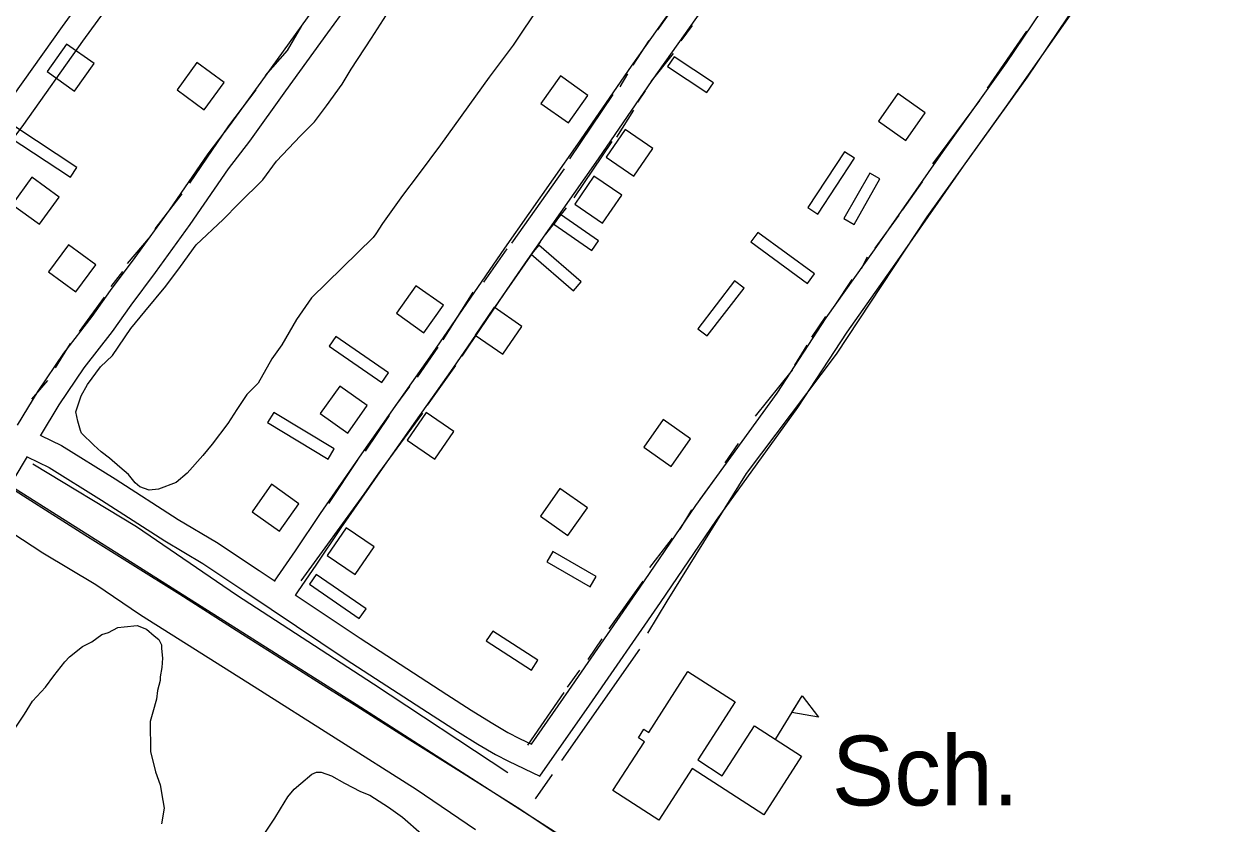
# Model space of a CAD drawing. Extents: x 3535183 to 3573198, y 534952 to 560562.
# Drawn here: x 3547982 to 3549418, y 545165 to 546115 of the extents above; entities that cross this region are included whole.
import ezdxf

# ---------------------------------------------------------------- set-up
doc = ezdxf.new("R2010")
doc.units = 0
for name, color, linetype in [('V-BLDG-IDEN', 7, 'Continuous'), ('V-BLDG-OTLN', 7, 'Continuous'), ('V-RAIL-TRAK', 7, 'Continuous'), ('V-ROAD-CNTR', 7, 'Continuous'), ('V-SITE-VEGE', 7, 'Continuous'), ('V-TOPO-SHOR', 7, 'Continuous')]:
    doc.layers.add(name, color=color, linetype=linetype)

msp = doc.modelspace()

# ---------------------------------------------------------------- linework, layer by layer
at = {"layer": 'V-BLDG-OTLN'}
msp.add_line((3548875.1, 545265.8), (3548906.1, 545317.2), dxfattribs=at)
for points in [[(3548032.1, 546091.2), (3548009, 546058.6), (3548041.7, 546035.5), (3548064.8, 546068.1)], [(3548793.1, 546033.7), (3548800.8, 546045.4), (3548754.1, 546076.2), (3548746.4, 546064.5)], [(3548195.7, 546013.3), (3548219.4, 546045.5), (3548187.1, 546069.2), (3548163.5, 546037)], [(3548628.5, 545997.6), (3548651.6, 546030.2), (3548619, 546053.4), (3548595.9, 546020.8)], [(3549029.5, 545976.6), (3549052.5, 546009.4), (3549019.8, 546032.4), (3548996.8, 545999.6)], [(3548036.8, 545933), (3548044.5, 545944.6), (3547971.7, 545992.7), (3547964, 545981)], [(3548696, 545989.9), (3548673.4, 545956.9), (3548706.4, 545934.3), (3548729, 545967.3)], [(3548913.2, 545897), (3548924.9, 545889.3), (3548968.4, 545955.7), (3548956.7, 545963.4)], [(3547999.8, 545877.2), (3548023.3, 545909.6), (3547990.9, 545933), (3547967.4, 545900.6)], [(3548658.9, 545934.2), (3548636.3, 545901.3), (3548669.2, 545878.6), (3548691.9, 545911.6)], [(3548955.9, 545883.9), (3548968.1, 545877), (3548998.7, 545931), (3548986.5, 545937.9)], [(3548656.4, 545846), (3548664.4, 545857.6), (3548619.2, 545888.8), (3548611.2, 545877.3)], [(3548853.6, 545867.5), (3548845.3, 545856.2), (3548912.6, 545807), (3548920.9, 545818.3)], [(3548043, 545796.9), (3548066.7, 545829.1), (3548034.5, 545852.8), (3548010.8, 545820.6)], [(3548634.6, 545798.2), (3548643.7, 545808.8), (3548593.4, 545852.3), (3548584.2, 545841.7)], [(3548456.7, 545748.4), (3548479.9, 545781), (3548447.3, 545804.2), (3548424.1, 545771.5)], [(3548782.4, 545753.1), (3548793.5, 545744.6), (3548837.2, 545801.5), (3548826, 545810)], [(3548540.2, 545778.6), (3548517.5, 545745.6), (3548550.5, 545723), (3548573.1, 545755.9)], [(3548352.1, 545743.9), (3548344.2, 545732.4), (3548406.8, 545689.2), (3548414.8, 545700.7)], [(3548366.2, 545629.2), (3548389.3, 545661.8), (3548356.7, 545685), (3548333.5, 545652.4)], [(3548278.3, 545653.8), (3548271, 545641.8), (3548342.9, 545598.3), (3548350.2, 545610.3)], [(3548459.3, 545653.8), (3548436.7, 545620.8), (3548469.6, 545598.2), (3548492.3, 545631.1)], [(3548750.7, 545589.6), (3548773.7, 545622.4), (3548741, 545645.3), (3548718, 545612.6)], [(3548285.1, 545512.7), (3548308.3, 545545.3), (3548275.7, 545568.4), (3548252.5, 545535.8)], [(3548628, 545507.6), (3548651, 545540.3), (3548618.2, 545563.3), (3548595.3, 545530.5)], [(3548364.5, 545516.6), (3548341.9, 545483.6), (3548374.9, 545461), (3548397.5, 545494)], [(3548610, 545488.5), (3548603, 545476.4), (3548654.5, 545446.6), (3548661.5, 545458.7)], [(3548380, 545409), (3548388, 545420.6), (3548328.8, 545461.2), (3548320.9, 545449.7)], [(3548538.5, 545394), (3548530.9, 545382.2), (3548584.6, 545347.7), (3548592.2, 545359.4)], [(3548826.5, 545309.8), (3548782.1, 545240.9), (3548811.3, 545222.1), (3548849.6, 545281.4), (3548905.6, 545245.3), (3548860.7, 545175.6), (3548775.4, 545230.6), (3548736, 545169.4), (3548681.4, 545204.6), (3548718.8, 545262.6), (3548711.8, 545267.1), (3548718.3, 545277.3), (3548724, 545273.6), (3548770.5, 545345.8)], [(3548906.1, 545317.2), (3548925.8, 545291.8), (3548894.2, 545297.4)]]:
    msp.add_lwpolyline(points, close=True, dxfattribs=at)
at = {"layer": 'V-RAIL-TRAK'}
msp.add_lwpolyline([(3547950.8, 545573.8), (3547985.3, 545552), (3548054, 545508.5), (3548110.8, 545472.7), (3548166.7, 545437.9), (3548233.7, 545395.1), (3548301.5, 545352.3), (3548341.6, 545326.8), (3548377.1, 545304.9), (3548436.8, 545266.8), (3548504.7, 545224.5), (3548567.4, 545185), (3548617.3, 545152)], dxfattribs=at)
at = {"layer": 'V-ROAD-CNTR'}
for points in [[(3549783, 548504.4), (3549676.2, 548359.9), (3549570.7, 548220.8), (3549457.8, 548069.1), (3549430.3, 548030.7), (3549356.4, 547927.2), (3549237.3, 547764.4), (3549120.1, 547605.6), (3548994.7, 547436.4), (3548915.5, 547331.8), (3548821.3, 547200.7), (3548722.7, 547067.2), (3548658.1, 546975.3), (3548586.3, 546878.4), (3548504.1, 546765.1), (3548454.3, 546692.9), (3548372.6, 546586), (3548290.4, 546473.6), (3548233.2, 546393.6), (3548168.8, 546306.2), (3548097.8, 546210.1), (3548026.7, 546112.1), (3547956.6, 546013.5)], [(3549446.2, 548001.3), (3549380.7, 547909.6), (3549261.5, 547746.6), (3549144.2, 547587.8), (3549018.7, 547418.4), (3548939.6, 547314), (3548845.6, 547183), (3548747.1, 547049.6), (3548682.4, 546957.7), (3548610.5, 546860.7), (3548528.6, 546747.8), (3548478.5, 546675.2), (3548396.6, 546568.1), (3548314.7, 546456), (3548257.5, 546376), (3548192.9, 546288.4), (3548122, 546192.3), (3548051.1, 546094.6), (3547980.9, 545995.8), (3547872.1, 545850.4), (3547819.9, 545780.2), (3547795.3, 545743.1)], [(3550407.3, 544022.4), (3550107.6, 544208.9), (3549713.8, 544462.2), (3549285.5, 544731.9), (3548967.9, 544929.2), (3548660.1, 545124.6), (3548376.2, 545306.9), (3547938.6, 545583), (3547735, 545714.5), (3547336.2, 545960.9), (3547019.4, 546160.3), (3546450.8, 546522.1), (3546030.5, 546792), (3545657.2, 547024.6), (3545377, 547202.9), (3545241.8, 547291.6), (3544939.7, 547479.7), (3544491.7, 547765.6), (3544295.4, 547891.8)], [(3549592.5, 547279.4), (3549546.2, 547215.7), (3549478.9, 547121.4), (3549417, 547032), (3549341.3, 546923.9), (3549252.5, 546794.5), (3549173.8, 546681), (3549119.4, 546607), (3549062.2, 546526.3), (3548977.2, 546404.6), (3548922.7, 546327.1), (3548852.5, 546226.7), (3548796.1, 546144.9), (3548727.8, 546047.9), (3548663.9, 545955.1), (3548577.1, 545831.6), (3548491.1, 545706.4), (3548407, 545587.2), (3548358.1, 545516.7), (3548328.5, 545472.4), (3548307.3, 545441.9), (3548304.3, 545437.2)], [(3549392.4, 547049.2), (3549316.6, 546941), (3549227.8, 546811.5), (3549149.3, 546698.5), (3549095, 546624.6), (3549037.7, 546543.6), (3548952.6, 546421.8), (3548898.1, 546344.3), (3548827.9, 546243.8), (3548771.5, 546162.1), (3548703.1, 546065), (3548639.3, 545972.2), (3548552.5, 545848.8), (3548466.5, 545723.6), (3548382.5, 545604.4), (3548333.4, 545533.6), (3548303.7, 545489.3), (3548282.4, 545458.5), (3548279, 545453.3)], [(3548303.8, 545437.1), (3548380.9, 545385.4), (3548483.9, 545318.7), (3548512.8, 545300.2), (3548536.5, 545285.4), (3548556.5, 545273.6), (3548570.5, 545266.4), (3548584.6, 545259.6), (3548629, 545323.2), (3548713.1, 545444.9), (3548779.8, 545543), (3548876.6, 545676.5), (3548935, 545765.9), (3548992.3, 545847), (3549073.7, 545963.6), (3549149.3, 546069), (3549221.5, 546176.5), (3549315.6, 546305.8), (3549341.6, 546343.7), (3549402.5, 546432.6), (3549529.1, 546614), (3549614.2, 546734.9), (3549701.7, 546857.3), (3549787, 546986)], [(3547973.7, 545638.6), (3547998.2, 545678.8), (3548028.8, 545724.2), (3548062.5, 545767.7), (3548084.5, 545798.6), (3548113.6, 545837.8), (3548154.4, 545894.1), (3548200.3, 545960.7), (3548225.7, 545994), (3548268.5, 546053.3), (3548318.3, 546122.3), (3548386.1, 546215.4), (3548442.7, 546292.8), (3548485.1, 546351.8), (3548530.9, 546415.7), (3548567.8, 546465.9), (3548609.7, 546523.7), (3548667.8, 546605), (3548709.7, 546662.3), (3548751.3, 546721.4), (3548778.1, 546758.5)], [(3548001.1, 545625.9), (3548023.5, 545662.6), (3548053.1, 545706.7), (3548086.5, 545749.8), (3548108.8, 545781), (3548137.8, 545820), (3548178.9, 545876.8), (3548224.6, 545943.1), (3548249.8, 545976.1), (3548292.8, 546035.8), (3548342.6, 546104.7), (3548410.3, 546197.7), (3548467, 546275.2), (3548509.5, 546334.4), (3548555.2, 546398.1), (3548592, 546448.2), (3548634, 546506.1), (3548692.1, 546587.4), (3548734.1, 546644.8), (3548775.7, 546704), (3548802.4, 546740.9)], [(3547985.1, 545601), (3548011.3, 545588.2), (3548073.8, 545549.5), (3548149, 545501.2), (3548194.2, 545474.2), (3548244.1, 545441), (3548275.2, 545420.2), (3548364.4, 545360.4), (3548467.7, 545293.5), (3548496.8, 545274.8), (3548521, 545259.8), (3548542, 545247.3), (3548557.1, 545239.5), (3548594.6, 545221.6), (3548653.6, 545306.1), (3548737.8, 545428), (3548804.4, 545525.8), (3548901.3, 545659.4), (3548959.8, 545749.1), (3549016.9, 545829.7), (3549098.2, 545946.3), (3549173.9, 546051.9), (3549246.1, 546159.3)], [(3548001.6, 545626.4), (3548025.9, 545614.5), (3548089.8, 545574.9), (3548164.8, 545526.7), (3548210.1, 545499.6), (3548260.8, 545466), (3548280, 545453.1)], [(3547970.9, 545576.8), (3547984.5, 545599.2), (3547985.7, 545601.2)]]:
    msp.add_lwpolyline(points, dxfattribs=at)
at = {"layer": 'V-SITE-VEGE'}
for points in [[(3548218.1, 545883), (3548236.8, 545902), (3548265.3, 545929.9), (3548281.7, 545952.2), (3548310.2, 545982.4), (3548326.7, 545999.1), (3548340.9, 546018.1), (3548359.5, 546043.7), (3548370.4, 546061.5), (3548394.4, 546098.3), (3548408.6, 546120.6), (3548418.5, 546136.1), (3548429.3, 546157.3), (3548450.1, 546185.1), (3548466.5, 546208.5), (3548490.6, 546245.3), (3548509.1, 546272), (3548537.7, 546303.3), (3548554, 546328.9), (3548577, 546362.3), (3548594.5, 546385.7), (3548620.7, 546423.6), (3548639.3, 546448.1)], [(3548616.4, 546170), (3548571.6, 546103.2), (3548562.8, 546089.8), (3548534.4, 546051.9), (3548476.4, 545971.7), (3548450.1, 545936), (3548431.5, 545911.5), (3548407.5, 545878.1), (3548399.8, 545865.8), (3548396.5, 545861.4), (3548323, 545789.8), (3548305.5, 545764.2), (3548288.1, 545734.2), (3548276, 545717.5), (3548259.7, 545688.5), (3548246.5, 545675.1), (3548234.5, 545657.3), (3548223.6, 545640.6), (3548205, 545616.1), (3548194, 545602.7), (3548175.4, 545581.5), (3548162.2, 545570.3), (3548141.2, 545562.4), (3548130.2, 545561.2), (3548119.1, 545565.5), (3548113.5, 545569.9), (3548105.6, 545579.8), (3548095.6, 545588.5), (3548083.3, 545599.5), (3548073.3, 545607.1), (3548064.4, 545614.8), (3548049.8, 545629.1), (3548048.7, 545632.4), (3548045.3, 545643.4), (3548043, 545654.5), (3548049.5, 545673.4), (3548057.1, 545686.7), (3548072.4, 545707.9), (3548086.7, 545721.3), (3548108.5, 545753.6), (3548125, 545773.7), (3548150.2, 545803.8), (3548167.7, 545827.2), (3548186.3, 545852.8), (3548218.1, 545883)], [(3547955.7, 545255.1), (3547982, 545295.2), (3547991.8, 545310.8), (3548007.1, 545327.5), (3548017, 545340.9), (3548030.1, 545357.6), (3548035.6, 545363.2), (3548051, 545375.5), (3548062, 545381.2), (3548074.1, 545390.1), (3548081.9, 545392.4), (3548092.9, 545398.1), (3548100.6, 545399.2), (3548116.1, 545400.5), (3548127.2, 545396.2), (3548136.1, 545388.5), (3548141.7, 545384.1), (3548145.1, 545377.5), (3548145.1, 545373.1), (3548146.3, 545362), (3548145.3, 545350.9), (3548143.2, 545339.8), (3548143.3, 545335.4), (3548140, 545323.2), (3548139, 545313.2), (3548134.7, 545297.7), (3548131.5, 545286.6), (3548131.8, 545251.1), (3548137.6, 545226.8), (3548143.3, 545211.4), (3548146.7, 545192.6), (3548147.9, 545183.8), (3548144.8, 545164.9)], [(3548267.8, 545153.8), (3548279.8, 545171.6), (3548286.3, 545182.8), (3548295.1, 545197.2), (3548302.7, 545206.2), (3548310.4, 545212.9), (3548323.6, 545224.1), (3548329.1, 545226.3), (3548334.7, 545226.4), (3548346.9, 545222.1), (3548362.5, 545213.3), (3548381.4, 545203.5), (3548392.5, 545199.2), (3548414.8, 545185), (3548431.5, 545173), (3548453.8, 545153.3)]]:
    msp.add_lwpolyline(points, dxfattribs=at)
at = {"layer": 'V-TOPO-SHOR'}
for p, q in [((3548766.1, 546153.3), (3548734.2, 546108.2)), ((3548775.7, 546113.2), (3548762.1, 546095.2)), ((3549173, 546106.5), (3549126.1, 546038.8)), ((3548723.9, 546095.7), (3548705.2, 546066.3)), ((3548752.8, 546079.9), (3548726.4, 546046.9)), ((3548698.9, 546055.8), (3548689.6, 546040.5)), ((3548681.4, 546031.3), (3548629.8, 545954.9)), ((3548719.9, 546035.9), (3548710.7, 546022.3)), ((3548706, 546012.9), (3548685.6, 545980.7)), ((3549116.9, 546024.3), (3549061, 545949)), ((3548680.2, 545975.6), (3548635, 545908.7)), ((3548623.3, 545943), (3548560.8, 545854.9)), ((3549048.9, 545927.8), (3549025, 545893.9)), ((3548169.1, 545913.3), (3548137.1, 545871.9)), ((3548625.9, 545896.8), (3548601.2, 545865.6)), ((3549021.3, 545887.9), (3548992.8, 545849)), ((3548131.5, 545862.5), (3548104.2, 545830.5)), ((3548555.3, 545848.2), (3548527.6, 545808.6)), ((3548983.7, 545838), (3548976.2, 545824.4)), ((3548098.6, 545821.2), (3548084.9, 545803.4)), ((3548965.3, 545811.8), (3548945, 545781.2)), ((3548076.6, 545790.7), (3548047.2, 545750)), ((3548515.1, 545796.7), (3548479.1, 545739.8)), ((3548934.1, 545767.7), (3548917.5, 545743.1)), ((3548036.2, 545735.7), (3548018.6, 545706.8)), ((3548473.5, 545731.3), (3548448.7, 545695.7)), ((3548911.9, 545733.8), (3548897.1, 545710)), ((3548494.4, 545709.6), (3548460.5, 545662.2)), ((3548894.3, 545704), (3548850.4, 545649.2)), ((3548009.3, 545691.5), (3547990.3, 545669.6)), ((3548439.6, 545684.7), (3548423.1, 545661.9)), ((3548415.6, 545650), (3548387.1, 545607.6)), ((3548830.1, 545616.9), (3548814.4, 545594)), ((3548378, 545597.5), (3548343.2, 545545.6)), ((3548803.3, 545576.2), (3548784.1, 545549.9)), ((3548774.9, 545538.1), (3548761, 545515.1)), ((3548751.9, 545504.2), (3548724.7, 545469.6)), ((3548716.9, 545453.3), (3548676.5, 545396.6)), ((3548668.2, 545384.7), (3548651.6, 545360.1)), ((3548713, 545372.6), (3548620.1, 545240.4)), ((3548641.6, 545347.5), (3548626.9, 545327.2)), ((3548623.2, 545321.2), (3548580, 545258.5)), ((3548609.1, 545223.5), (3548588.8, 545194.7))]:
    msp.add_line(p, q, dxfattribs=at)
for points in [[(3549325, 546267.4), (3549237.3, 546144.2), (3549148.6, 546017.6), (3549054.4, 545885.9), (3548946.5, 545723), (3548839.8, 545581), (3548745.4, 545429.7), (3548722.4, 545391.4)], [(3548311.4, 546113.1), (3548294.1, 546083.6), (3548268.3, 546053.9)], [(3548257.2, 546036.9), (3548224.6, 545994), (3548178.3, 545926)], [(3548594.8, 545856.3), (3548552.3, 545795.1), (3548523.7, 545753.1), (3548501.8, 545720.6)], [(3548454.9, 545652.8), (3548402.9, 545581.6), (3548385.4, 545556.6), (3548310.6, 545453.8)], [(3547992.2, 545592.7), (3548115.4, 545518.1), (3548234.1, 545437), (3548396.7, 545331.3), (3548556.4, 545226.1)], [(3547816.4, 545352.2), (3547849.3, 545398.6), (3547900, 545470), (3547942.5, 545527.1), (3548004, 545486.9), (3548066.9, 545449.3), (3548119.9, 545413.4)], [(3548119.9, 545413.4), (3548255, 545328.3), (3548447.7, 545206.2), (3548517.9, 545158.2)]]:
    msp.add_lwpolyline(points, dxfattribs=at)

# ---------------------------------------------------------------- texts
at = {"layer": 'V-BLDG-IDEN'}
msp.add_text('Sch.', height=83, dxfattribs=at).set_placement((3548941.6, 545186.8))

doc.saveas('drawing.dxf')
